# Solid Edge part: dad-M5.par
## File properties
Title: 1320500090
Subject: Dado esagonale M5
Author: g_deluca
Template: Zama.par
Last saved by: b_giovanelli
Revision: 9
Application: Solid Edge
Tipo di contenuto documento: 0
Material: Classe 8
Coef. of Thermal Exp: 0.0
Thermal Conductivity: 0.0
Specific Heat: 0.0
Modulus of Elasticity: 0.0
Poission's Ratio: 0.0
Yield Stress: 0.0
Ultimate Stress: 0.0
Elongation: 0.0
Company: EFFEBI S.p.A.
custom2: 2001-08-01
Densità: 7860.000 kg/m^3
Precisione: 0.99
Document Number: UNI 5588-65
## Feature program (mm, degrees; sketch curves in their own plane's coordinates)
sketch for "unnamed Protrusion 1" plane through (0, 0, 0) normal (0, 0, 1) x-axis (1, 0, 0)
  line (-2.3094, 4) -> (2.3094, 4)
  line (2.3094, 4) -> (4.6188, 0)
  line (4.6188, 0) -> (2.3094, -4)
  line (2.3094, -4) -> (-2.3094, -4)
  line (-2.3094, -4) -> (-4.6188, 0)
  line (-4.6188, 0) -> (-2.3094, 4)
extrude "unnamed Protrusion 1" add finite 4 symmetric
sketch for "Hole_1" plane through (0, 0, 2) normal (0, 0, 1) x-axis (-1, 0, 0)
  hole centre (0, 0) bore radius 2.1
hole "Hole_1" nominal diameter 5 through  ThreadDepth = 2 mm
sketch for "unnamed RevolvedCutout 1" plane through (0, 0, 0) normal (1, 0, 0) x-axis (0, 1, 0)
  line (-1.0312, -3.5212) -> (-7.1301, 0)
  line (-7.1301, 0) -> (-1.0312, 3.5212)
revolve "unnamed RevolvedCutout 1" cut finite 360 deg
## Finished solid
Body 1: solid body, 11 faces, 22 edges, 12 vertices.
  Faces by surface: plane 8, cone 2, cylinder 1
  Edges by curve: intersection 12, line 6, circle 4
Bounding box of the edges (mm): 9.238 x 8.000 x 4.000, from (-4.6188, -4, -2) to (4.6188, 4, 2).
Cylindrical faces by radius (mm): R2.1 x1
Conical faces (half-angle, radius in mm at the cone's reference point): 60 deg R1.0312 x1, 60 deg R7.1301 x1
Planar faces by outward normal: +y 1, +z 1, -y 1, -z 1, oblique 4
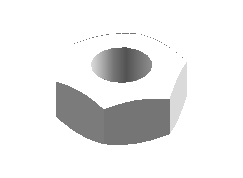
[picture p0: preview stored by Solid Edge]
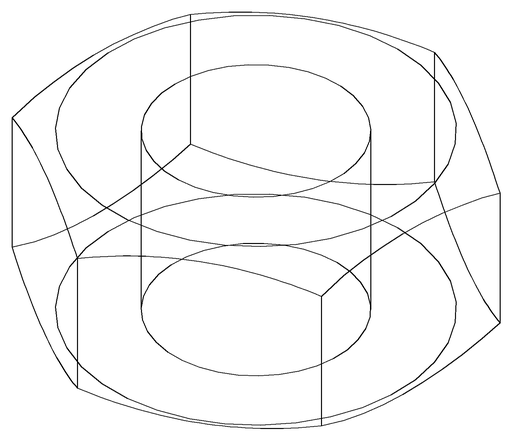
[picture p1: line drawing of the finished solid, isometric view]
